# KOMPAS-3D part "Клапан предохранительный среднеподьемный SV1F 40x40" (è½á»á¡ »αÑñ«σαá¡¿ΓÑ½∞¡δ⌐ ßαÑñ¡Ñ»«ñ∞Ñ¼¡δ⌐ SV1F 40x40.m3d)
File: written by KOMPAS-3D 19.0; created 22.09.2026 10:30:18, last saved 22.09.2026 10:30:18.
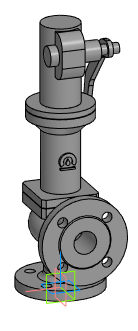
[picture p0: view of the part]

Document properties: Автор: Евгений; Полное имя файла: Z:\3.Личные\sachek\Dendor\_3D для проектировщиков\5.8 SV1F. Клапан предохранительный среднеподьемный\SV1F_STP\Клапан предохранительный среднеподьемный SV1F 40x40.m3d

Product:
- Part/product: Клапан предохранительный среднеподьемный SV1F 40x40
    Масса: 26.5532

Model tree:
1. Операция без истории:1  (labels: Клапан предохранительный среднеподьемный SV1F 40x40)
